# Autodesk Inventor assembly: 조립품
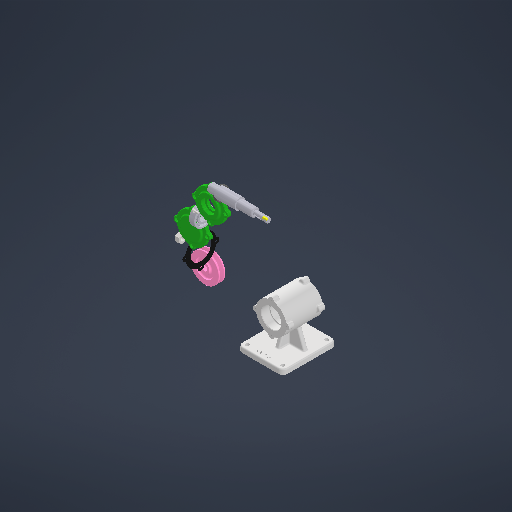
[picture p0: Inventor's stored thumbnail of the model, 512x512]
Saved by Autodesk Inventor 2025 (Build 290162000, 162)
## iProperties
Created: 2025-08
Part Number: 조립품
Document SubType Name: Assembly
Designer: infra17
Author: infra17
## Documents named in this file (12)
- C:\Users\infra17\Desktop\750806V1008\조립품.iam
- C:\Users\infra17\Desktop\750806V1008\본체.ipt
- C:\Users\infra17\Desktop\750806V1008\V-벨트풀리\V-벨트풀리.ipt
- C:\Users\infra17\Desktop\750806V1008\개스킷\개스킷.ipt
- C:\Users\infra17\Desktop\750806V1008\너트 M12 x 1.25\너트 M12 x 1.25.ipt
- C:\Users\infra17\Desktop\750806V1008\뒤커버\뒤커버.ipt
- C:\Users\infra17\Desktop\750806V1008\베어링 6204\베어링 6204.ipt
- C:\Users\infra17\Desktop\750806V1008\볼트 M4 x 12\볼트 M4 x 12.ipt
- C:\Users\infra17\Desktop\750806V1008\앞커버\앞커버.ipt
- C:\Users\infra17\Desktop\750806V1008\오일 실\오일 실.ipt
- C:\Users\infra17\Desktop\750806V1008\축\축.ipt
- C:\Users\infra17\Desktop\750806V1008\키 4 x 4\키 4 x 4.ipt
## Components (2 placed, 2 different names)
1. V-벨트풀리:1
2. 개스킷:1
